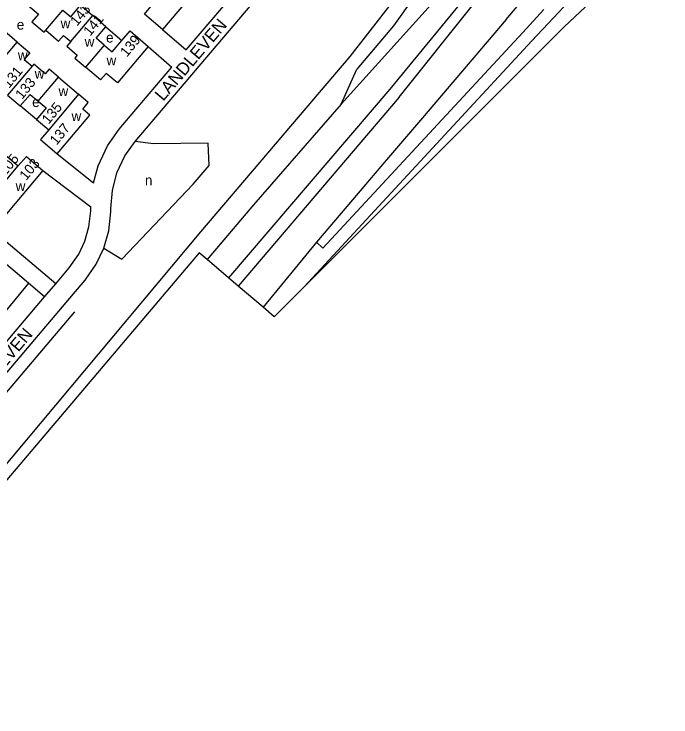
# Model space of a CAD drawing. Extents: x 155696 to 157795, y 382328 to 384028.
# Drawn here: x 156980.5 to 157241.7, y 382327.9 to 382607.2 of the extents above; entities that cross this region are included whole.
import ezdxf

# ---------------------------------------------------------------- set-up
doc = ezdxf.new("R2010")
doc.units = 0
for name, color, linetype in [('BLT_Basislijn', 7, 'Continuous'), ('BLT_Bebouwing', 7, 'Continuous'), ('BLT_Centroide', 7, 'Continuous'), ('BLT_Gemeentegrens', 7, 'Continuous'), ('BLT_Huisnummer', 7, 'Continuous'), ('BLT_Huisnummer_ tussenligend', 7, 'Continuous'), ('BLT_Onderverdeling_panden', 7, 'Continuous'), ('BLT_Straatnaam', 7, 'Continuous')]:
    doc.layers.add(name, color=color, linetype=linetype)

msp = doc.modelspace()

# ---------------------------------------------------------------- linework, layer by layer
at = {"layer": 'BLT_Basislijn'}
for p, q in [((157143.83, 382628.71), (157114.07, 382590.29)), ((157155.62, 382621.34), (157110.52, 382571.36)), ((157161.9, 382616.37), (157129.89, 382577.42)), ((157133.69, 382574.17), (157163.26, 382611.09)), ((157017.01, 382602.18), (157023.41, 382596.65)), ((157039.55, 382601.07), (157048.94, 382592.94)), ((157186.46, 382596.52), (157095.83, 382498.79)), ((157033.85, 382594.37), (157043.23, 382586.13)), ((157114.07, 382590.29), (157054.68, 382520.73)), ((156997.06, 382500.08), (156894.28, 382586.82)), ((157025.21, 382564.87), (157043.23, 382586.13)), ((157110.52, 382571.36), (157116.77, 382585.33)), ((156986.19, 382500.27), (156892.45, 382580.02)), ((157129.89, 382577.42), (157065.77, 382502.4)), ((157133.69, 382574.17), (157069.64, 382499.12)), ((157110.52, 382571.36), (157075.69, 382531.36)), ((156989.39, 382565.3), (156982.98, 382570.71)), ((156997.65, 382551.7), (157012.12, 382540.19)), ((156991.99, 382545.05), (157011.03, 382530.62)), ((157075.69, 382531.36), (157057.24, 382509.64)), ((157054.68, 382520.73), (156894.99, 382330.24)), ((156992.6, 382494.82), (156986.19, 382500.27)), ((156992.6, 382494.82), (156997.06, 382500.08)), ((156950.61, 382425.19), (157004.61, 382488.89))]:
    msp.add_line(p, q, dxfattribs=at)
for points in [[(157048.94, 382592.94), (157070.3, 382618.06), (157070.69, 382618.62), (157070.95, 382619.18), (157071.09, 382619.81), (157071.1, 382620.41), (157071.01, 382620.88), (157070.79, 382621.48), (157070.44, 382622.01), (157069.92, 382622.56), (156985.4, 382694.2)], [(157228.8, 382634.84), (157224.41, 382632.7), (157220.27, 382630.26), (157216.33, 382627.55), (157212.71, 382624.5), (157204.98, 382616.49), (157195.01, 382605.74)], [(157028.66, 382556.57), (157076.63, 382613.16), (157077.66, 382614.62), (157078.57, 382616.63), (157079.07, 382618.87), (157079.11, 382621.03), (157078.77, 382623), (157077.97, 382625.1)], [(157147.8, 382625.68), (157131.46, 382602.59), (157116.77, 382585.33)], [(157176.14, 382605), (157184.25, 382614.78)], [(157191.18, 382608.96), (157182.8, 382599.92)], [(157176.14, 382605), (157142.88, 382565.96), (157128.65, 382549.28)], [(157195.01, 382605.74), (157186.46, 382596.52)], [(157182.8, 382599.92), (157103.28, 382514.17), (157100.74, 382516.53)], [(157012.12, 382540.19), (157013.89, 382546.91), (157017.66, 382554.9), (157022.34, 382561.48), (157025.21, 382564.87)], [(157016.18, 382514.15), (157018.17, 382521.11), (157018.99, 382528.58), (157019, 382529.99), (157019.59, 382537.15), (157021.44, 382544.16), (157024.6, 382550.85), (157028.66, 382556.57)], [(157016.18, 382514.15), (157023.37, 382509.86), (157051.71, 382539.66), (157058.05, 382547.09), (157057.68, 382555.93), (157035.99, 382555.66), (157028.66, 382556.57)], [(157128.65, 382549.28), (157115.09, 382533.38), (157100.74, 382516.53)], [(156997.06, 382500.08), (157002.4, 382506.39), (157006.25, 382511.86), (157008.67, 382516.98), (157010.3, 382522.65), (157010.99, 382529.05), (157011.01, 382530.35), (157011.03, 382530.62)], [(157100.74, 382516.53), (157079.54, 382490.72)], [(157004.11, 382496.03), (157008.74, 382501.49), (157013.19, 382507.82), (157016.18, 382514.15)], [(156986.19, 382500.27), (156934.07, 382436.84), (156913.01, 382454.14)], [(156943.34, 382424.34), (157004.11, 382496.03)], [(156910.88, 382445.17), (156931.52, 382427.68), (156932.08, 382427.28), (156932.61, 382427.04), (156933.21, 382426.9), (156933.85, 382426.89), (156934.44, 382427), (156934.92, 382427.19), (156935.4, 382427.49), (156936.02, 382428.08), (156992.6, 382494.82)]]:
    msp.add_lwpolyline(points, dxfattribs=at)
at = {"layer": 'BLT_Bebouwing'}
for p, q in [((157006.94, 382610.75), (157011.83, 382606.59)), ((157017.01, 382602.18), (157011.83, 382606.59)), ((156998.14, 382582.15), (157006.18, 382575.35)), ((156994.27, 382561.17), (156991.05, 382557.33)), ((156991.05, 382557.33), (156997.65, 382551.7)), ((156982.12, 382546.87), (156985.39, 382550.66)), ((156985.39, 382550.66), (156991.99, 382545.05))]:
    msp.add_line(p, q, dxfattribs=at)
for points in [[(157046.55, 382623.93), (157047.55, 382625.11), (157050.96, 382622.22), (157048.77, 382619.63), (157052.54, 382616.38), (157039.55, 382601.07)], [(156986.03, 382610.72), (156990.16, 382607.21), (156987.58, 382604.15), (156992.48, 382600), (156993.15, 382600.75)], [(156999.92, 382608.79), (157003.02, 382606.16), (157006.94, 382610.75)], [(157039.55, 382601.07), (157032.35, 382607.17), (157035.58, 382610.99)], [(156981.69, 382596.1), (156973.63, 382602.93), (156971.54, 382600.74)], [(157016.35, 382594.88), (157013.11, 382597.62), (157017.01, 382602.18)], [(156993.15, 382600.75), (156998.23, 382596.46), (157000.15, 382598.73), (157003.06, 382596.29)], [(157023.41, 382596.65), (157026.7, 382600.53), (157033.85, 382594.37)], [(156981.69, 382596.1), (156986.74, 382591.81), (156984.51, 382589.18), (156987.66, 382586.48)], [(157003.06, 382596.29), (157001.44, 382594.39), (157005.62, 382590.83), (157004.67, 382589.67), (157008.9, 382586.08)], [(157016.35, 382594.88), (157019.58, 382592.14), (157023.41, 382596.65)], [(157033.85, 382594.37), (157021.61, 382579.93), (157017.18, 382583.65), (157014.82, 382581.06), (157008.9, 382586.08)], [(156998.14, 382582.15), (156994.47, 382585.29), (156992.84, 382583.4), (156988.33, 382587.27), (156987.66, 382586.48)], [(156977.95, 382574.98), (156982.98, 382570.71)], [(156982.98, 382570.71), (156986.87, 382575.29), (156990.08, 382572.59)], [(156997.65, 382551.7), (157010.59, 382567), (157007.79, 382569.38), (157010.03, 382572.06), (157006.18, 382575.35)], [(156990.08, 382572.59), (156993.28, 382569.89), (156989.39, 382565.3)], [(156989.39, 382565.3), (156994.27, 382561.17)], [(156977.27, 382551), (156982.12, 382546.87)], [(156991.99, 382545.05), (156977.45, 382527.89), (156970.86, 382533.51), (156972.79, 382535.79)]]:
    msp.add_lwpolyline(points, dxfattribs=at)
at = {"layer": 'BLT_Gemeentegrens'}
for points in [[(157241.73, 382631.47), (157237.68, 382630.76), (157234.44, 382630.19), (157226.69, 382627.08), (157221.78, 382623.36), (157211.98, 382614.24), (157199.26, 382602.09), (157095.83, 382498.79)], [(157057.24, 382509.64), (157054.13, 382512.28), (156977.61, 382422.16), (156897.72, 382327.92), (156894.99, 382330.24)], [(157065.77, 382502.4), (157057.24, 382509.64)], [(157069.64, 382499.12), (157065.77, 382502.4)], [(157079.54, 382490.72), (157069.64, 382499.12)], [(157095.83, 382498.79), (157083.98, 382486.95), (157079.54, 382490.72)]]:
    msp.add_lwpolyline(points, dxfattribs=at)
at = {"layer": 'BLT_Onderverdeling_panden'}
for p, q in [((156993.15, 382600.75), (156999.92, 382608.79)), ((157003.06, 382596.29), (157011.83, 382606.59)), ((156973.61, 382586.52), (156981.69, 382596.1)), ((157016.35, 382594.88), (157008.9, 382586.08)), ((156987.66, 382586.48), (156977.95, 382574.98)), ((156990.08, 382572.59), (156998.14, 382582.15)), ((157006.18, 382575.35), (156994.27, 382561.17)), ((156972.79, 382535.79), (156982.12, 382546.87))]:
    msp.add_line(p, q, dxfattribs=at)

# ---------------------------------------------------------------- texts
at = {"layer": 'BLT_Centroide'}
for s, p in [('w', (156999.02, 382601.52)), ('e', (156981.59, 382601.01)), ('e', (157017.09, 382595.91)), ('w', (157008.58, 382594.2)), ('w', (156982.01, 382588.89)), ('w', (157017.29, 382586.81)), ('w', (156988.7, 382581.55)), ('w', (156998.19, 382574.64)), ('e', (156987.71, 382570.3)), ('w', (157003.36, 382564.71)), ('n', (157032.55, 382539.19)), ('w', (156981.15, 382536.86))]:
    msp.add_text(s, height=4, dxfattribs=at).set_placement(p)
at = {"layer": 'BLT_Huisnummer'}
for s, rotation, p in [('143', 50.5022, (157005.54, 382602.16)), ('139', 50.5751, (157025.37, 382589.89)), ('133', 50.5751, (156983.7, 382573.03)), ('137', 50.5751, (156997.4, 382554.84)), ('103', 50.5751, (156985.34, 382540.87))]:
    msp.add_text(s, height=4, rotation=rotation, dxfattribs=at).set_placement(p)
at = {"layer": 'BLT_Huisnummer_ tussenligend'}
for s, rotation, p in [('141', 51.0247, (157010.78, 382598.19)), ('131', 50.5751, (156978.52, 382577.48)), ('135', 50.5751, (156994.24, 382563.16)), ('105', 50.5751, (156977.07, 382542.72))]:
    msp.add_text(s, height=4, rotation=rotation, dxfattribs=at).set_placement(p)
at = {"layer": 'BLT_Straatnaam'}
for p in [(157039.81, 382572.33), (156962.51, 382449.46)]:
    msp.add_text('LANDLEVEN', height=5, rotation=49.7122, dxfattribs=at).set_placement(p)

doc.saveas('drawing.dxf')
